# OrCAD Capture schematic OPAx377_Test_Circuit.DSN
size A; title: OPAx377, 5MHz, Low-Noise,Single, Dual, Quad CMOS; rev: 1.1; note: Datasheet:SBOS504B EVM: NA
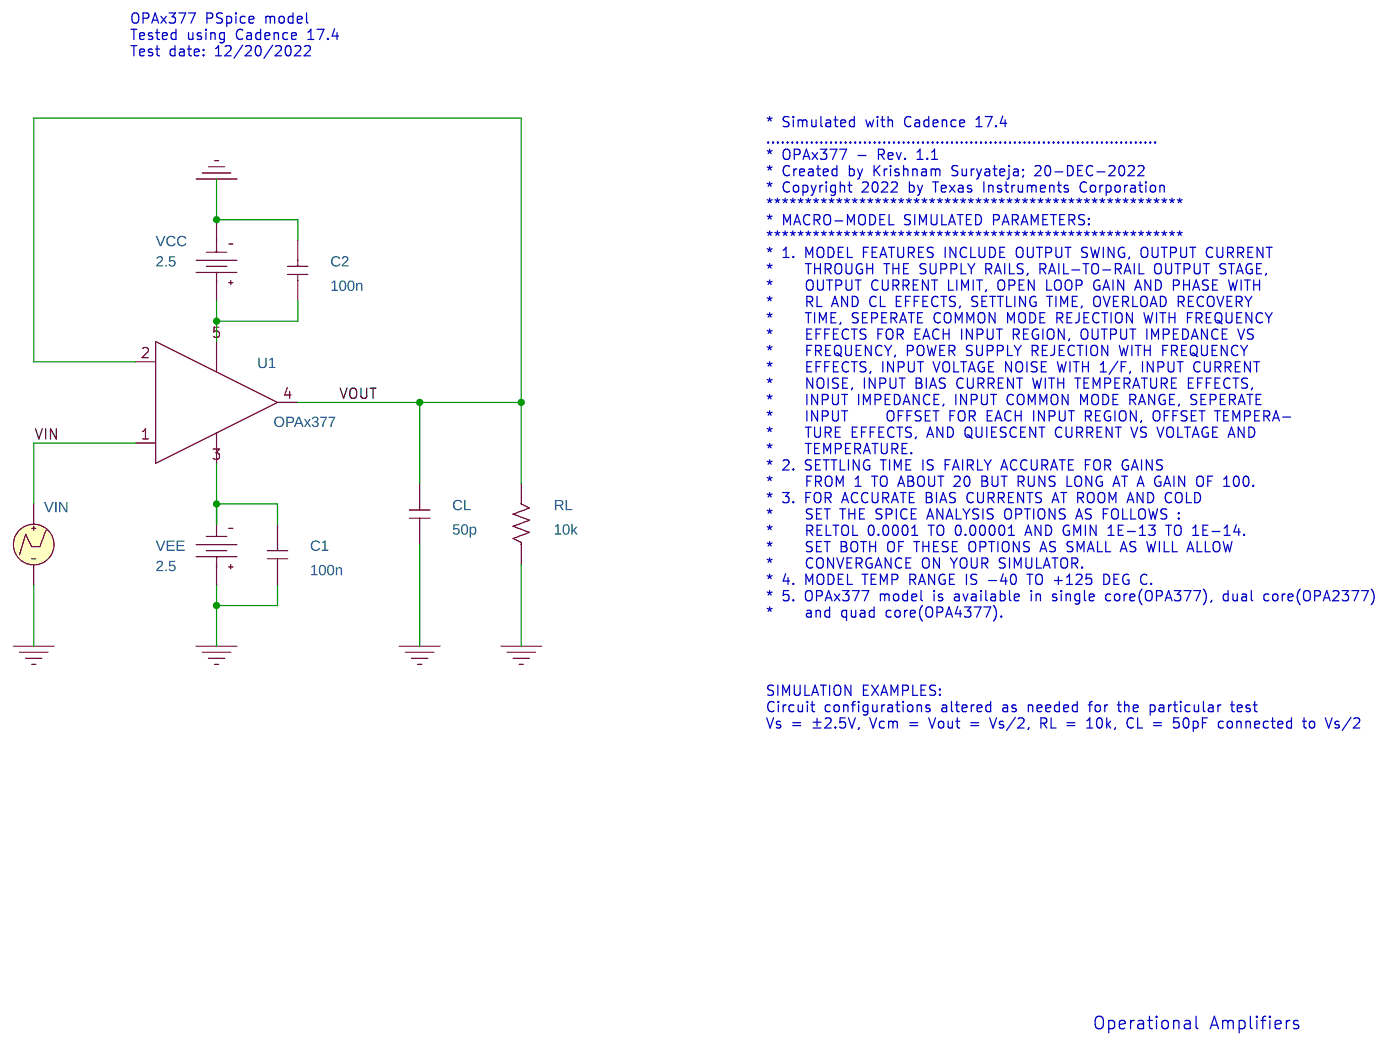
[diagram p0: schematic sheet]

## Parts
C1  100n  [RAD/CK05]
C2  100n  [RAD/CK05]
CL  50p  [RAD/CK05]
RL  10k  [AX/RC05]
U1  OPAx377
VCC  VDC
VEE  VDC
VIN  VPWL

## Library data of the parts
C1 C2 CL = C
RL = R
U1 = OPAx377
VCC VEE = VDC: DC: 2.5
VIN = VPWL: AC: 1; T1: 0; T2: 0.1n; T3: 1u; T4: 1.01u; T5: 2u; T6: 2.01u; T7: 3u; T8: 3.01u; V1: 0; V2: 0.1; V3: 0.1; V4: -0.1; V5: -0.1; V6: 0.1; V7: 0.1; V8: -0.1

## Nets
VIN: U1.1(+) VIN.1(+)
0: C1.1 C2.2 CL.1 RL.1 VCC.1(-) VEE.0(+) VIN.2(-)
VOUT: CL.2 RL.2 U1.2(-) U1.4(OUT)
N14309457: C2.1 U1.5(V+) VCC.0(+)
N14309541: C1.2 U1.3(V-) VEE.1(-)

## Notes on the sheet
- OPAx377 PSpice model
  Tested using Cadence 17.4
  Test date: 12/20/2022
- * Simulated with Cadence 17.4
  .................................................................................
  * OPAx377 - Rev. 1.1
  * Created by Krishnam Suryateja; 20-DEC-2022
  * Copyright 2022 by Texas Instruments Corporation
  ******************************************************
  * MACRO-MODEL SIMULATED PARAMETERS:
  ******************************************************
  * 1. MODEL FEATURES INCLUDE OUTPUT SWING, OUTPUT CURRENT
  *    THROUGH THE SUPPLY RAILS, RAIL-TO-RAIL OUTPUT STAGE,
  *    OUTPUT CURRENT LIMIT, OPEN LOOP GAIN AND PHASE WITH
  *    RL AND CL EFFECTS, SETTLING TIME, OVERLOAD RECOVERY
  *    TIME, SEPERATE COMMON MODE REJECTION WITH FREQUENCY
  *    EFFECTS FOR EACH INPUT REGION, OUTPUT IMPEDANCE VS
  *    FREQUENCY, POWER SUPPLY REJECTION WITH FREQUENCY
  *    EFFECTS, INPUT VOLTAGE NOISE WITH 1/F, INPUT CURRENT
  *    NOISE, INPUT BIAS CURRENT WITH TEMPERATURE EFFECTS,
  *    INPUT IMPEDANCE, INPUT COMMON MODE RANGE, SEPERATE
  *    INPUT	OFFSET FOR EACH INPUT REGION, OFFSET TEMPERA-
  *    TURE EFFECTS, AND QUIESCENT CURRENT VS VOLTAGE AND
  *    TEMPERATURE.
  * 2. SETTLING TIME IS FAIRLY ACCURATE FOR GAINS
  *    FROM 1 TO ABOUT 20 BUT RUNS LONG AT A GAIN OF 100.
  * 3. FOR ACCURATE BIAS CURRENTS AT ROOM AND COLD
  *    SET THE SPICE ANALYSIS OPTIONS AS FOLLOWS :
  *    RELTOL 0.0001 TO 0.00001 AND GMIN 1E-13 TO 1E-14.
  *    SET BOTH OF THESE OPTIONS AS SMALL AS WILL ALLOW
  *    CONVERGANCE ON YOUR SIMULATOR.
  * 4. MODEL TEMP RANGE IS -40 TO +125 DEG C.
  * 5. OPAx377 model is available in single core(OPA377), dual core(OPA2377)
  *    and quad core(OPA4377).
- SIMULATION EXAMPLES:
  Circuit configurations altered as needed for the particular test
  Vs = ±2.5V, Vcm = Vout = Vs/2, RL = 10k, CL = 50pF connected to Vs/2
- Operational Amplifiers
